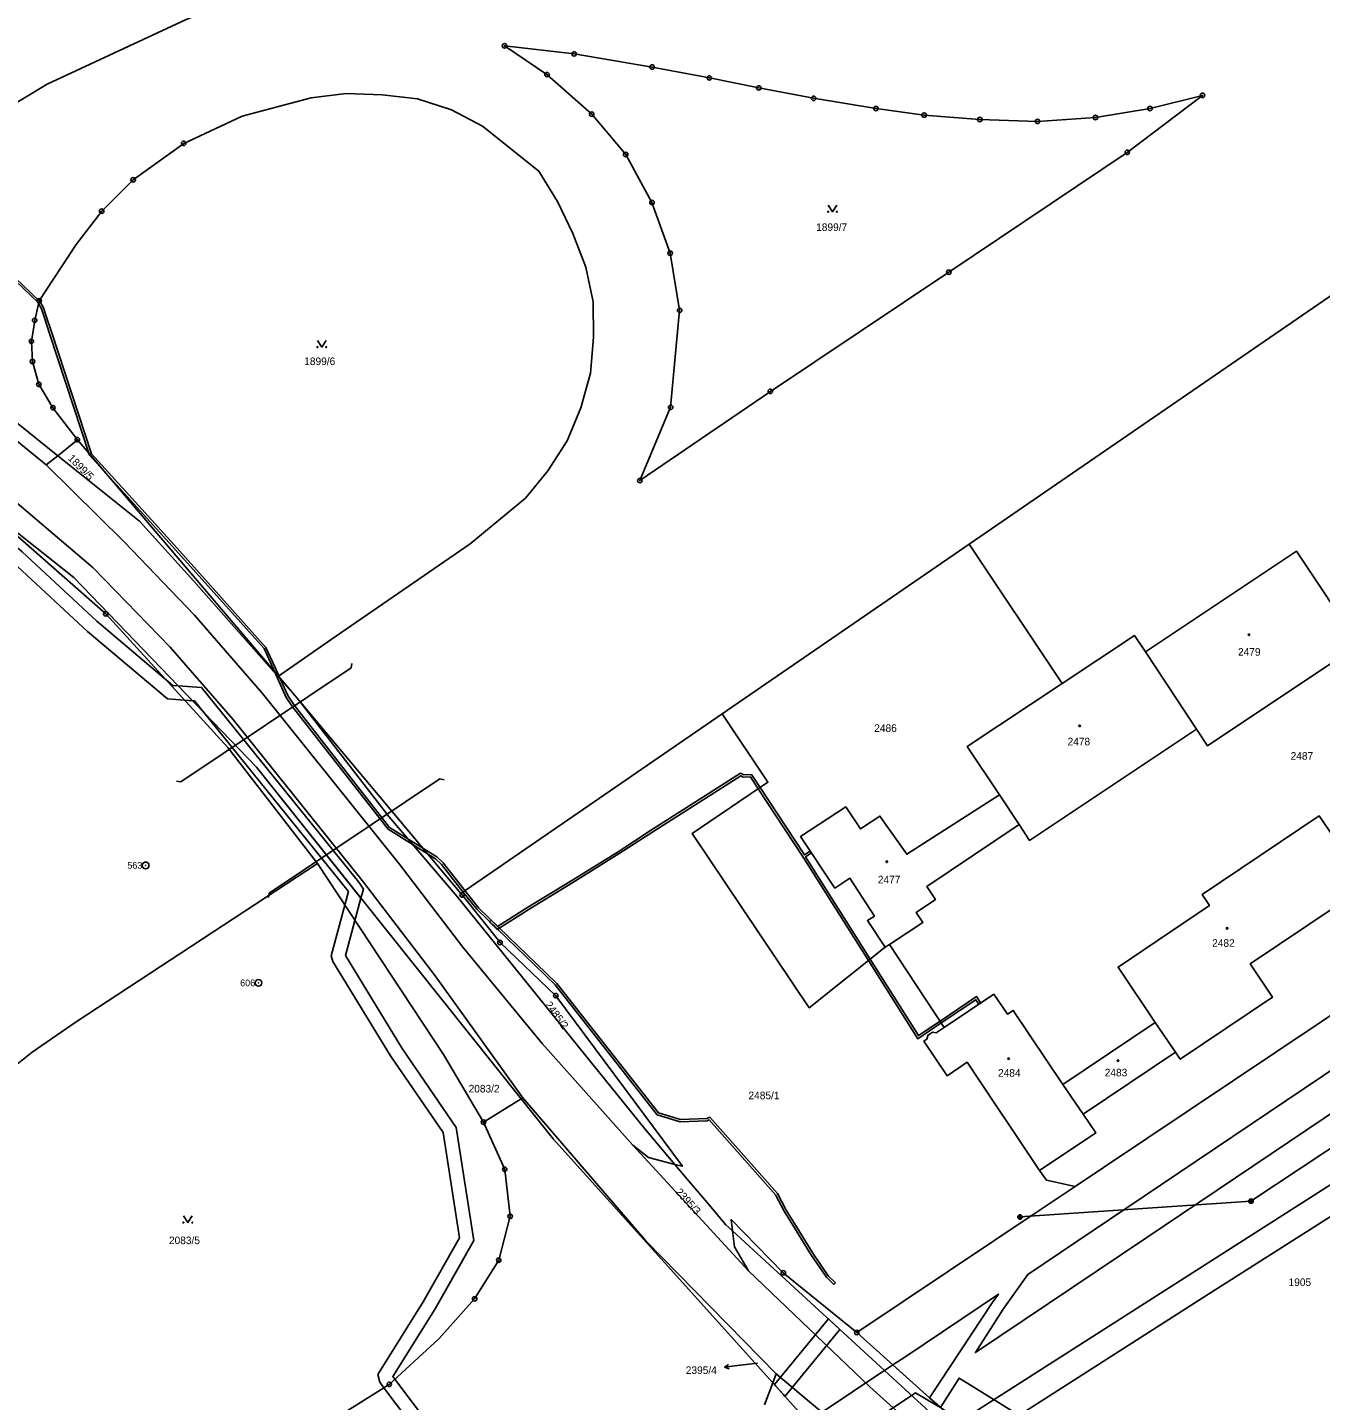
# Model space of a CAD drawing. Extents: x -504988 to -494607, y -1123820 to -1114018.
# Drawn here: x -502218.8 to -501929, y -1120555.7 to -1120247.9 of the extents above; entities that cross this region are included whole.
import ezdxf

# ---------------------------------------------------------------- set-up
doc = ezdxf.new("R2010")
doc.units = 0
for name, color, linetype in [('Hranice parcel', 7, 'Continuous'), ('Parcelní čísla', 7, 'Continuous'), ('Pop  PČ popisy', 7, 'Continuous'), ('Poz předměty', 7, 'Continuous'), ('Vnitřní kresba', 7, 'Continuous'), ('Věcná břemena k části', 7, 'Continuous'), ('Značky bodu BP', 7, 'Continuous'), ('Značky budov', 7, 'Continuous'), ('Značky kultur', 7, 'Continuous')]:
    doc.layers.add(name, color=color, linetype=linetype)

msp = doc.modelspace()

# ---------------------------------------------------------------- linework, layer by layer
at = {"layer": 'Hranice parcel'}
for p, q in [((-501885.37, -1120279.59), (-502007.81, -1120363.74)), ((-502207.66, -1120340.34), (-502212.07, -1120343.92)), ((-502162.6, -1120393.32), (-502207.66, -1120340.34)), ((-502007.81, -1120363.74), (-502063.14, -1120401.77)), ((-501986.92, -1120394.96), (-502007.81, -1120363.74)), ((-501956.82, -1120405.23), (-501968.27, -1120387.88)), ((-502157.99, -1120398.75), (-502162.6, -1120393.32)), ((-502121.72, -1120442.04), (-502157.99, -1120398.75)), ((-502063.14, -1120401.77), (-502121.72, -1120442.04)), ((-501996.59, -1120426.61), (-502001.01, -1120419.9)), ((-502026.58, -1120454.11), (-502025.66, -1120453.5)), ((-502025.66, -1120453.5), (-502013.36, -1120472.07)), ((-501966.09, -1120470.93), (-501986.76, -1120484.83)), ((-501966.09, -1120470.93), (-501961.52, -1120477.65)), ((-501982.23, -1120491.53), (-501961.52, -1120477.65)), ((-501986.76, -1120484.83), (-501982.23, -1120491.53)), ((-502108.19, -1120488.06), (-502116.62, -1120493.3)), ((-502053.67, -1120556.69), (-502051.78, -1120551.73))]:
    msp.add_line(p, q, dxfattribs=at)
for points in [[(-502280, -1120281.82), (-502274.63, -1120284.13), (-502246.47, -1120279.94), (-502214.41, -1120260.61), (-502183.27, -1120246.15), (-502168.2, -1120240.13), (-502151.2, -1120235.11), (-502123.83, -1120230.69), (-502118.28, -1120230.16), (-502084.78, -1120230.92), (-502034.44, -1120241.52), (-502007.97, -1120244.89), (-502003.99, -1120244.9)], [(-502078.87, -1120287.16), (-502084.76, -1120276.42), (-502092.38, -1120267.36), (-502102.4, -1120258.5), (-502111.91, -1120252.06), (-502096.3, -1120253.87), (-502078.84, -1120256.8), (-502066, -1120259.25), (-502054.93, -1120261.49), (-502042.64, -1120263.81), (-502028.64, -1120266.1), (-502017.86, -1120267.58), (-502005.4, -1120268.57), (-501992.45, -1120268.99), (-501979.47, -1120268.11), (-501967.24, -1120266.11), (-501955.47, -1120263.16), (-501972.34, -1120275.93), (-502012.33, -1120302.78), (-502052.34, -1120329.5), (-502081.58, -1120349.5), (-502074.68, -1120333.08), (-502072.67, -1120311.33), (-502074.79, -1120298.54), (-502078.87, -1120287.16)], [(-502207.66, -1120340.34), (-502213.13, -1120333.17), (-502216.29, -1120327.92), (-502217.72, -1120322.81), (-502217.96, -1120318.29), (-502217.22, -1120313.6), (-502216.2, -1120309.19), (-502207.95, -1120296.59), (-502202.2, -1120289.1), (-502195.15, -1120282.09), (-502183.82, -1120273.91), (-502170.7, -1120267.81), (-502155.26, -1120263.69), (-502147.4, -1120262.72), (-502139.37, -1120263), (-502131.43, -1120263.96), (-502123.79, -1120266.43), (-502116.85, -1120270.08), (-502104.26, -1120280.11), (-502100.04, -1120286.91), (-502096.58, -1120294.15), (-502093.72, -1120301.68), (-502092.07, -1120309.46), (-502091.98, -1120317.46), (-502092.63, -1120325.41), (-502094.81, -1120333.19), (-502097.88, -1120340.62), (-502102.19, -1120347.32), (-502107.18, -1120353.42), (-502119.61, -1120363.65), (-502150.74, -1120385.14), (-502162.6, -1120393.32)], [(-502108.19, -1120488.06), (-502167.48, -1120413.77), (-502208.47, -1120371.26), (-502251.12, -1120337.46), (-502305.92, -1120299.91), (-502351.1, -1120272.04)], [(-502153.81, -1120435.32), (-502173.91, -1120409.33), (-502201.29, -1120379.36), (-502225.38, -1120358.23), (-502257.25, -1120334.48), (-502294.89, -1120308.03), (-502347.35, -1120275.72), (-502351.1, -1120272.04)], [(-502212.07, -1120343.92), (-502214.62, -1120345.98), (-502246.73, -1120319.91), (-502284.88, -1120292.06), (-502283.35, -1120288.83)], [(-502212.07, -1120343.92), (-502220.95, -1120336.8), (-502221.98, -1120335.97), (-502263.9, -1120302.44), (-502269.81, -1120298.31), (-502283.35, -1120288.83)], [(-502212.07, -1120343.92), (-502193.73, -1120358.63), (-502181.53, -1120372.07), (-502157.99, -1120398.75)], [(-501956.82, -1120405.23), (-501954.37, -1120408.92), (-501920.44, -1120386.33), (-501934.42, -1120365.34), (-501968.27, -1120387.88)], [(-501968.27, -1120387.88), (-501970.74, -1120384.19), (-501986.92, -1120394.96)], [(-501812.1, -1120392.65), (-501977.66, -1120503.44), (-501984.01, -1120507.69)], [(-501986.92, -1120394.96), (-502008.2, -1120409.12), (-502001.01, -1120419.9)], [(-502073.72, -1120502.77), (-502080.44, -1120494.81), (-502122.61, -1120442.65), (-502137.83, -1120424.82), (-502157.99, -1120398.75)], [(-502063.14, -1120401.77), (-502052.89, -1120417.13), (-502069.89, -1120428.62), (-502043.63, -1120467.69), (-502026.58, -1120454.11)], [(-501996.59, -1120426.61), (-501994.24, -1120430.14), (-501956.82, -1120405.23)], [(-502001.01, -1120419.9), (-502021.77, -1120433.26), (-502027.78, -1120424.71), (-502032.12, -1120427.59), (-502035.44, -1120422.6), (-502045.55, -1120429.29), (-502037.88, -1120440.84), (-502034.51, -1120438.65), (-502029.01, -1120447.11), (-502030.57, -1120448.13), (-502026.58, -1120454.11)], [(-501961.52, -1120477.65), (-501960.48, -1120479.2), (-501939.81, -1120465.31), (-501944.79, -1120457.83), (-501918.73, -1120440.37), (-501920.35, -1120437.9), (-501917.25, -1120435.86), (-501920.9, -1120430.31), (-501924.06, -1120432.45), (-501929.3, -1120424.65), (-501955.52, -1120442.25), (-501953.93, -1120444.72), (-501974.4, -1120458.53), (-501966.09, -1120470.93)], [(-502025.66, -1120453.5), (-502018.13, -1120448.52), (-502019.64, -1120446.29), (-502015.33, -1120443.41), (-502017.27, -1120440.49), (-501996.59, -1120426.61)], [(-502116.62, -1120493.3), (-502111.87, -1120503.89), (-502110.66, -1120514.41), (-502113.21, -1120524.23), (-502118.61, -1120532.92), (-502126.56, -1120541.77), (-502137.75, -1120552.07), (-502153.61, -1120562.04), (-502169.26, -1120567.84), (-502186.99, -1120572.33), (-502202.53, -1120573.64), (-502216.55, -1120571.21), (-502227.8, -1120566.34), (-502236.81, -1120559), (-502243.57, -1120549.16), (-502247.78, -1120537.86), (-502249.1, -1120525.97), (-502247.45, -1120514.13), (-502242.87, -1120503.04), (-502235.89, -1120493.27), (-502227.17, -1120485.08), (-502217.79, -1120477.64), (-502207.89, -1120470.82), (-502153.81, -1120435.32)], [(-502153.81, -1120435.32), (-502125.57, -1120478.12), (-502116.62, -1120493.3)], [(-502121.72, -1120442.04), (-502121.43, -1120442.38), (-502112.93, -1120453.04), (-502100.42, -1120464.96), (-502072.06, -1120503.2), (-502073.72, -1120502.77)], [(-501986.76, -1120484.83), (-501997.91, -1120468.24), (-501999.22, -1120469.07), (-502002.23, -1120464.64), (-502013.36, -1120472.07)], [(-502013.36, -1120472.07), (-502015.14, -1120473.26), (-502015.98, -1120473.13), (-502017.05, -1120473.86), (-502017.24, -1120474.72), (-502017.93, -1120475.13), (-502012.74, -1120482.92), (-502008.2, -1120479.89), (-501992, -1120504.15)], [(-502108.19, -1120488.06), (-502107.84, -1120487.84), (-502080.27, -1120519.93), (-502051.01, -1120549.7), (-502051.78, -1120551.73)], [(-502051.78, -1120551.73), (-502101.04, -1120497.02), (-502108.19, -1120488.06)], [(-501992, -1120504.15), (-501979.42, -1120495.71), (-501982.23, -1120491.53)], [(-502060.8, -1120517.68), (-502060.34, -1120521.25), (-502057.2, -1120526.62), (-502083.13, -1120498.44), (-502079.63, -1120501.24), (-502073.72, -1120502.77)], [(-502060.8, -1120517.68), (-502062.31, -1120516.29), (-502066.5, -1120511.33), (-502070.95, -1120506.05), (-502073.72, -1120502.77)], [(-501992, -1120504.15), (-501990.45, -1120506.31), (-501984.01, -1120507.69)], [(-501984.01, -1120507.69), (-501991.64, -1120512.8), (-502032.97, -1120540.46)], [(-502060.8, -1120517.68), (-502061.12, -1120515.15), (-502049.43, -1120527.09), (-502032.97, -1120540.46)], [(-501934.6, -1120621.3), (-501951.32, -1120611.56), (-502000.17, -1120572.5), (-502013.82, -1120560.86), (-502060.8, -1120517.68)], [(-502032.97, -1120540.46), (-502016.66, -1120555.09), (-501993.19, -1120575.45)], [(-501974.82, -1120612.22), (-501983.91, -1120607.29), (-502010.39, -1120592.19), (-502037.96, -1120567.09), (-502051.78, -1120551.73)]]:
    msp.add_lwpolyline(points, dxfattribs=at)
at = {"layer": 'Pop  PČ popisy'}
for p, q in [((-502062.65, -1120548.24), (-502061.72, -1120547.62)), ((-502059.67, -1120547.87), (-502062.65, -1120548.24)), ((-502062.65, -1120548.24), (-502061.59, -1120548.61)), ((-502055.18, -1120547.3), (-502059.67, -1120547.87))]:
    msp.add_line(p, q, dxfattribs=at)
at = {"layer": 'Poz předměty'}
for p, q in [((-501871.37, -1120462.27), (-501944.61, -1120511)), ((-501944.61, -1120511), (-501996.4, -1120514.55))]:
    msp.add_line(p, q, dxfattribs=at)
for centre, radius in [((-501944.61, -1120511), 0.5), ((-501944.61, -1120511), 0.4), ((-501944.61, -1120511), 0.3), ((-501944.61, -1120511), 0.2), ((-501944.61, -1120511), 0.1), ((-501996.4, -1120514.55), 0.5), ((-501996.4, -1120514.55), 0.4), ((-501996.4, -1120514.55), 0.3), ((-501996.4, -1120514.55), 0.2), ((-501996.4, -1120514.55), 0.1)]:
    msp.add_circle(centre, radius, dxfattribs=at)
at = {"layer": 'Vnitřní kresba'}
for p, q in [((-502204.15, -1120369.04), (-502234.14, -1120343.52)), ((-502197.18, -1120363.21), (-502214.62, -1120345.98)), ((-502181.43, -1120379.65), (-502197.18, -1120363.21)), ((-502204.15, -1120369.04), (-502186.88, -1120386.84)), ((-502166.18, -1120397.2), (-502181.43, -1120379.65)), ((-502186.88, -1120386.84), (-502172.78, -1120403)), ((-502184.49, -1120417.05), (-502146.32, -1120391.46)), ((-502146.13, -1120390.48), (-502146.32, -1120391.46)), ((-502166.18, -1120397.2), (-502135.5, -1120435.37)), ((-502143.56, -1120439.53), (-502172.78, -1120403)), ((-502185.47, -1120416.86), (-502184.49, -1120417.05)), ((-502164.64, -1120441.99), (-502126.44, -1120416.36)), ((-502125.46, -1120416.55), (-502126.44, -1120416.36)), ((-502135.5, -1120435.37), (-502121.23, -1120454.1)), ((-502143.56, -1120439.53), (-502127.48, -1120460.51)), ((-502164.83, -1120442.97), (-502164.64, -1120441.99)), ((-502121.23, -1120454.1), (-502103.45, -1120475.66)), ((-502107.84, -1120487.84), (-502127.48, -1120460.51)), ((-502103.45, -1120475.66), (-502083.13, -1120498.44)), ((-502057.2, -1120526.62), (-502030.06, -1120552.6)), ((-502019.83, -1120575.86), (-502051.01, -1120549.7)), ((-502030.06, -1120552.6), (-502013.06, -1120567.9))]:
    msp.add_line(p, q, dxfattribs=at)
at = {"layer": 'Věcná břemena k části'}
for points in [[(-502340.64, -1120291.06), (-502324.66, -1120295.11), (-502285.74, -1120321.67), (-502266.79, -1120335.56), (-502247.35, -1120348.26), (-502234.27, -1120357.36), (-502222.09, -1120367.82), (-502205.38, -1120383.34), (-502187.48, -1120398.45), (-502181.87, -1120398.85), (-502185.08, -1120395.51), (-502186.26, -1120395.43), (-502203.32, -1120381.02), (-502220.03, -1120365.5), (-502232.37, -1120354.9), (-502245.61, -1120345.68), (-502265.03, -1120333.02), (-502283.94, -1120319.13), (-502323.36, -1120292.25), (-502339.44, -1120288.16), (-502354.98, -1120278.88), (-502355.07, -1120279.03), (-502356.11, -1120281.82)], [(-502179.86, -1120395.88), (-502185.08, -1120395.51), (-502181.87, -1120398.85), (-502181.42, -1120398.88), (-502179.25, -1120401.56), (-502167.48, -1120413.77), (-502144.09, -1120443.08), (-502143.56, -1120441.11), (-502144.54, -1120439.48)], [(-502137.49, -1120478.45), (-502125.7, -1120495.65), (-502122.03, -1120519.22), (-502130.15, -1120533.55), (-502140.29, -1120549.86), (-502139.87, -1120551.6), (-502138.95, -1120552.82), (-502119.6, -1120578.49), (-502116.86, -1120576.98), (-502136.51, -1120550.93), (-502136.94, -1120550.35), (-502127.49, -1120535.13), (-502118.81, -1120519.82), (-502122.74, -1120494.47), (-502134.89, -1120476.77), (-502147.54, -1120455.97), (-502144.09, -1120443.08), (-502167.48, -1120413.77), (-502179.25, -1120401.56), (-502146.9, -1120441.57), (-502150.78, -1120456.05), (-502150.38, -1120457.27)], [(-502115.29, -1120448.38), (-502113.56, -1120450.11), (-502106.64, -1120445.7), (-502096.59, -1120439.59), (-502086.2, -1120433.1), (-502078.67, -1120428.22), (-502067.4, -1120421.06), (-502058.98, -1120415.67), (-502058.41, -1120415.96), (-502056.82, -1120415.9), (-502055.05, -1120418.59), (-502044.98, -1120433.88), (-502030.33, -1120457.1), (-502019.29, -1120474.6), (-502014.02, -1120471.07), (-502006.25, -1120465.86), (-502005.58, -1120466.87), (-502005.16, -1120466.6), (-502006.11, -1120465.16), (-502014.3, -1120470.65), (-502019.15, -1120473.9), (-502029.94, -1120456.79), (-502044.43, -1120433.81), (-502043.12, -1120432.95), (-502043.4, -1120432.53), (-502044.7, -1120433.39), (-502054.63, -1120418.31), (-502056.56, -1120415.38), (-502058.29, -1120415.46), (-502059, -1120415.09), (-502067.66, -1120420.64), (-502078.95, -1120427.8), (-502086.46, -1120432.68), (-502096.85, -1120439.17), (-502106.9, -1120445.28), (-502113.5, -1120449.47), (-502114.94, -1120448.03)], [(-501875.35, -1120456.87), (-501851.7, -1120431.36), (-501912.56, -1120472.21), (-501972.67, -1120512.68), (-501994.65, -1120527.45), (-502000.16, -1120535.23), (-502006.36, -1120544.95), (-501968.21, -1120519.32), (-501908.1, -1120478.85)], [(-501956.88, -1120526.52), (-502010.27, -1120560.63), (-502005.54, -1120564.73), (-501953.66, -1120531.58), (-501912.11, -1120505.08), (-501902.12, -1120491.59)], [(-502002.6, -1120533.8), (-502001.21, -1120531.85), (-502021.98, -1120545.81), (-502024.86, -1120547.73), (-502016.66, -1120555.09)], [(-502036.75, -1120539.78), (-502037.12, -1120539.44), (-502039, -1120537.72), (-502039.34, -1120537.41), (-502051.43, -1120552.13), (-502051.11, -1120552.49), (-502049.4, -1120554.38), (-502049.06, -1120554.76)], [(-502035.36, -1120564.35), (-502019.83, -1120553.99), (-502017.02, -1120555.64), (-502014.22, -1120557.28), (-502016.66, -1120555.09), (-502024.86, -1120547.73), (-502042.98, -1120559.82)], [(-501969.73, -1120584.85), (-501965.06, -1120578.33), (-501975.27, -1120571.98), (-501995.7, -1120559.58), (-502005.51, -1120553.45), (-502010, -1120550.67), (-502014.22, -1120557.28), (-502009.73, -1120560.25), (-501999.88, -1120566.4), (-501979.45, -1120578.8)]]:
    msp.add_lwpolyline(points, close=True, dxfattribs=at)
msp.add_lwpolyline([(-502247.37, -1120280.07), (-502216.47, -1120309.6), (-502216.35, -1120309.83), (-502215.72, -1120311), (-502215.12, -1120312.83), (-502213.89, -1120316.56), (-502204.93, -1120343.77), (-502195.76, -1120353.88), (-502185.66, -1120365.01), (-502165.81, -1120387.16), (-502163.78, -1120391.65), (-502160.87, -1120398.09), (-502159.42, -1120400.18), (-502138.03, -1120427.64), (-502127.38, -1120434.26), (-502126.05, -1120435.55), (-502120.93, -1120442.04), (-502118.06, -1120445.67), (-502109.18, -1120454.23), (-502107.38, -1120455.97), (-502100.56, -1120462.56), (-502077.71, -1120491.64), (-502072.55, -1120493.22), (-502066.48, -1120492.97), (-502066.06, -1120492.8), (-502051.18, -1120509.57), (-502049.21, -1120513.25), (-502046.9, -1120517.01), (-502043.23, -1120522.98), (-502039.75, -1120528.06), (-502038.1, -1120529.67), (-502037.75, -1120529.32), (-502039.37, -1120527.74), (-502042.81, -1120522.7), (-502046.57, -1120516.58), (-502048.77, -1120513.01), (-502050.76, -1120509.29), (-502065.92, -1120492.2), (-502066.58, -1120492.47), (-502072.49, -1120492.72), (-502077.41, -1120491.2), (-502100.18, -1120462.22), (-502107.08, -1120455.57), (-502108.87, -1120453.83), (-502117.68, -1120445.33), (-502120.51, -1120441.75), (-502125.67, -1120435.21), (-502127.08, -1120433.86), (-502137.69, -1120427.26), (-502159.02, -1120399.88), (-502160.43, -1120397.85), (-502162.51, -1120393.26), (-502163.42, -1120391.24), (-502165.39, -1120386.88), (-502185.28, -1120364.67), (-502195.41, -1120353.52), (-502204.49, -1120343.51), (-502213.49, -1120316.16), (-502214.72, -1120312.42), (-502215.26, -1120310.8), (-502216.07, -1120309.3), (-502216.19, -1120309.18), (-502246.75, -1120279.98)], dxfattribs=at)
at = {"layer": 'Značky bodu BP'}
for centre, radius in [((-502111.91, -1120252.06), 0.5), ((-502111.91, -1120252.06), 0.0303), ((-502096.3, -1120253.87), 0.5), ((-502096.3, -1120253.87), 0.0303), ((-502102.4, -1120258.5), 0.5), ((-502102.4, -1120258.5), 0.0303), ((-502078.84, -1120256.8), 0.5), ((-502078.84, -1120256.8), 0.0303), ((-502066, -1120259.25), 0.5), ((-502066, -1120259.25), 0.0303), ((-502054.93, -1120261.49), 0.5), ((-502054.93, -1120261.49), 0.0303), ((-502042.64, -1120263.81), 0.5), ((-502042.64, -1120263.81), 0.0303), ((-501955.47, -1120263.16), 0.5), ((-501955.47, -1120263.16), 0.0303), ((-502092.38, -1120267.36), 0.5), ((-502092.38, -1120267.36), 0.0303), ((-502028.64, -1120266.1), 0.5), ((-502028.64, -1120266.1), 0.0303), ((-502017.86, -1120267.58), 0.5), ((-502017.86, -1120267.58), 0.0303), ((-502005.4, -1120268.57), 0.5), ((-501992.45, -1120268.99), 0.5), ((-501979.47, -1120268.11), 0.5), ((-501979.47, -1120268.11), 0.0303), ((-501967.24, -1120266.11), 0.5), ((-501967.24, -1120266.11), 0.0303), ((-502005.4, -1120268.57), 0.0303), ((-501992.45, -1120268.99), 0.0303), ((-502183.82, -1120273.91), 0.5), ((-502183.82, -1120273.91), 0.0303), ((-502084.76, -1120276.42), 0.5), ((-502084.76, -1120276.42), 0.0303), ((-501972.34, -1120275.93), 0.5), ((-501972.34, -1120275.93), 0.0303), ((-502195.15, -1120282.09), 0.5), ((-502195.15, -1120282.09), 0.0303), ((-502078.87, -1120287.16), 0.5), ((-502202.2, -1120289.1), 0.5), ((-502202.2, -1120289.1), 0.0303), ((-502078.87, -1120287.16), 0.0303), ((-502074.79, -1120298.54), 0.5), ((-502074.79, -1120298.54), 0.0303), ((-502012.33, -1120302.78), 0.5), ((-502012.33, -1120302.78), 0.0303), ((-502216.2, -1120309.19), 0.5), ((-502216.2, -1120309.19), 0.0303), ((-502072.67, -1120311.33), 0.5), ((-502072.67, -1120311.33), 0.0303), ((-502217.22, -1120313.6), 0.5), ((-502217.22, -1120313.6), 0.0303), ((-502217.96, -1120318.29), 0.5), ((-502217.96, -1120318.29), 0.0303), ((-502217.72, -1120322.81), 0.5), ((-502217.72, -1120322.81), 0.0303), ((-502216.29, -1120327.92), 0.5), ((-502216.29, -1120327.92), 0.0303), ((-502052.34, -1120329.5), 0.5), ((-502052.34, -1120329.5), 0.0303), ((-502213.13, -1120333.17), 0.5), ((-502074.68, -1120333.08), 0.5), ((-502074.68, -1120333.08), 0.0303), ((-502213.13, -1120333.17), 0.0303), ((-502207.66, -1120340.34), 0.5), ((-502207.66, -1120340.34), 0.0303), ((-502081.58, -1120349.5), 0.5), ((-502081.58, -1120349.5), 0.0303), ((-502201.29, -1120379.36), 0.5), ((-502201.29, -1120379.36), 0.0303), ((-502192.35, -1120435.75), 0.75), ((-502192.35, -1120435.75), 0.03), ((-502121.43, -1120442.38), 0.5), ((-502121.43, -1120442.38), 0.0303), ((-502112.93, -1120453.04), 0.5), ((-502112.93, -1120453.04), 0.0303), ((-502167.06, -1120462.09), 0.75), ((-502167.06, -1120462.09), 0.03), ((-502100.42, -1120464.96), 0.5), ((-502100.42, -1120464.96), 0.0303), ((-502116.62, -1120493.3), 0.5), ((-502116.62, -1120493.3), 0.0303), ((-502111.87, -1120503.89), 0.5), ((-502111.87, -1120503.89), 0.0303), ((-502110.66, -1120514.41), 0.5), ((-502110.66, -1120514.41), 0.0303), ((-502113.21, -1120524.23), 0.5), ((-502113.21, -1120524.23), 0.0303), ((-502049.43, -1120527.09), 0.5), ((-502049.43, -1120527.09), 0.0303), ((-502118.61, -1120532.92), 0.5), ((-502118.61, -1120532.92), 0.0303), ((-502032.97, -1120540.46), 0.5), ((-502032.97, -1120540.46), 0.0303), ((-502137.75, -1120552.07), 0.5), ((-502137.75, -1120552.07), 0.0303)]:
    msp.add_circle(centre, radius, dxfattribs=at)
at = {"layer": 'Značky budov'}
for centre in [(-501945.07, -1120384.06), (-501983.03, -1120404.48), (-502026.22, -1120434.93), (-501949.96, -1120449.87), (-501998.92, -1120479.05), (-501974.4, -1120479.52)]:
    msp.add_circle(centre, 0.175, dxfattribs=at)
at = {"layer": 'Značky kultur'}
for points in [[(-502039.41, -1120287.74), (-502038.41, -1120289.24), (-502037.41, -1120287.74)], [(-502153.86, -1120318.08), (-502152.86, -1120319.58), (-502151.86, -1120318.08)], [(-502183.89, -1120514.3), (-502182.89, -1120515.8), (-502181.89, -1120514.3)]]:
    msp.add_lwpolyline(points, dxfattribs=at)
for centre in [(-502039.41, -1120289.24), (-502037.41, -1120289.24), (-502153.86, -1120319.58), (-502151.86, -1120319.58), (-502183.89, -1120515.8), (-502181.89, -1120515.8)]:
    msp.add_circle(centre, 0.1, dxfattribs=at)

# ---------------------------------------------------------------- texts
at = {"layer": 'Parcelní čísla'}
for s, p in [('1899/7', (-502042.07, -1120293.55)), ('1899/6', (-502156.81, -1120323.61)), ('2479', (-501947.52, -1120388.74)), ('2486', (-502029.05, -1120405.83)), ('2478', (-501985.72, -1120408.85)), ('2487', (-501935.73, -1120412.07)), ('2477', (-502028.25, -1120439.79)), ('2482', (-501953.32, -1120454)), ('2484', (-502001.31, -1120483.12)), ('2483', (-501977.4, -1120483.04)), ('2083/2', (-502119.97, -1120486.65)), ('2485/1', (-502057.24, -1120488.16)), ('2083/5', (-502187.13, -1120520.65)), ('1905', (-501936.19, -1120530.03)), ('2395/4', (-502071.29, -1120549.75))]:
    msp.add_text(s, height=1.7, dxfattribs=at).set_placement(p)
for s, rotation, p in [('1899/5', 315, (-502209.9, -1120344.66)), ('2485/2', 306, (-502102.93, -1120466.99)), ('2395/3', 312, (-502073.7, -1120509.04))]:
    msp.add_text(s, height=1.7, rotation=rotation, dxfattribs=at).set_placement(p)
at = {"layer": 'Značky bodu BP'}
for s, p in [('563', (-502196.45, -1120436.5)), ('606', (-502171.16, -1120462.84))]:
    msp.add_text(s, height=1.5, dxfattribs=at).set_placement(p)

doc.saveas('drawing.dxf')
